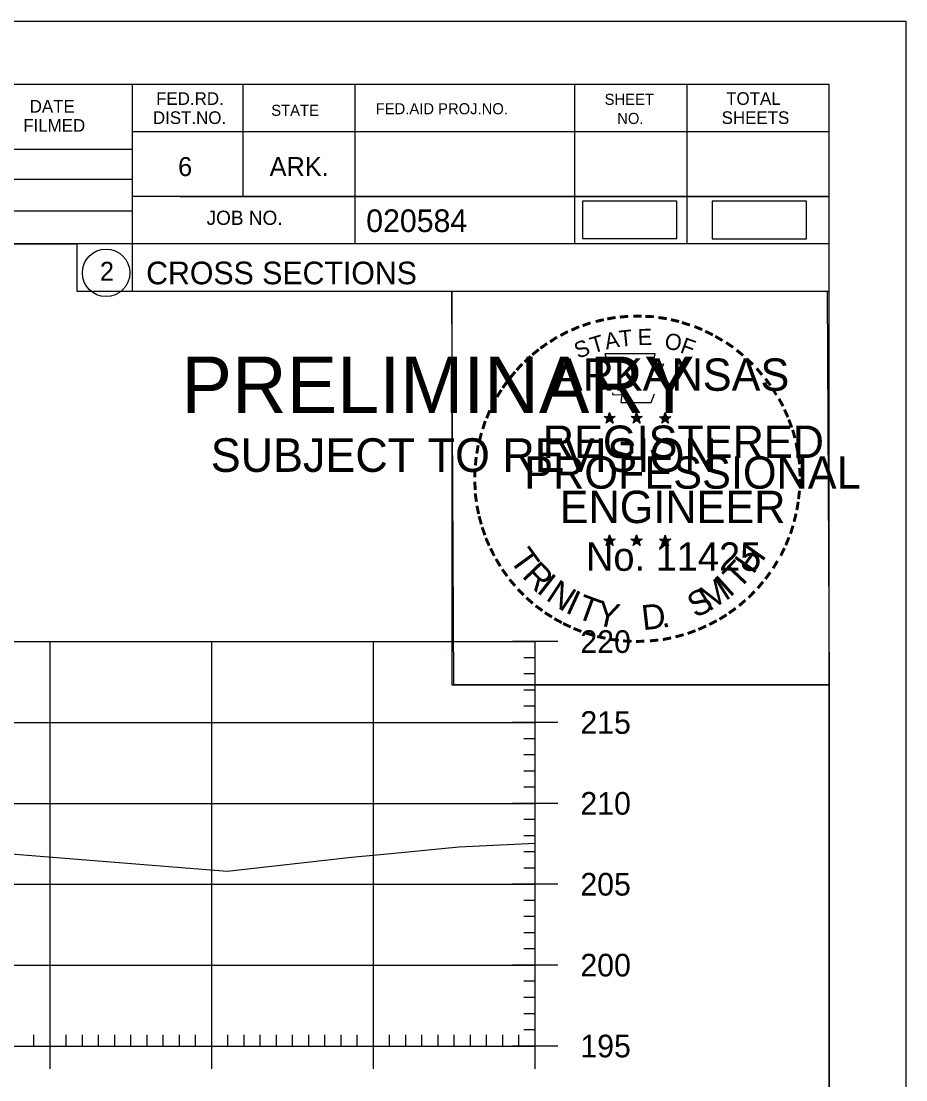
# Model space of a CAD drawing. Extents: x 1312042 to 1371461, y 379929 to 1834241.
# Drawn here: x 1371406.5 to 1371461.2, y 380076.8 to 380142.3 of the extents above; entities that cross this region are included whole.
import ezdxf

# ---------------------------------------------------------------- set-up
doc = ezdxf.new("R2010")
doc.units = 0
for name, color, linetype in [('Default', 7, 'Continuous'), ('R_Axis', 7, 'Continuous'), ('R_Axis Annot', 7, 'Continuous'), ('R_Border', 7, 'Continuous'), ('R_Border PE', 7, 'Continuous'), ('R_Border Prem', 7, 'Continuous'), ('R_Exist Surface', 7, 'Continuous'), ('R_Grid', 7, 'Continuous'), ('R_No Plot', 7, 'Continuous')]:
    doc.layers.add(name, color=color, linetype=linetype)

msp = doc.modelspace()

# ---------------------------------------------------------------- linework, layer by layer
at = {"layer": 'Default'}
for points in [[(1371441.216, 380128.825), (1371447.049, 380128.825), (1371447.049, 380131.136), (1371441.216, 380131.136)], [(1371449.239, 380128.818), (1371455.073, 380128.818), (1371455.073, 380131.128), (1371449.239, 380131.128)]]:
    msp.add_lwpolyline(points, close=True, dxfattribs=at)
at = {"layer": 'R_Axis'}
for p, q in [((1371439.677, 380103.909), (1371436.877, 380103.909)), ((1371438.277, 380078.909), (1371438.277, 380103.909)), ((1371438.277, 380102.909), (1371437.577, 380102.909)), ((1371438.277, 380101.909), (1371437.577, 380101.909)), ((1371438.277, 380100.909), (1371437.577, 380100.909)), ((1371438.277, 380099.909), (1371437.577, 380099.909)), ((1371439.677, 380098.909), (1371436.877, 380098.909)), ((1371438.277, 380097.909), (1371437.577, 380097.909)), ((1371438.277, 380096.909), (1371437.577, 380096.909)), ((1371438.277, 380095.909), (1371437.577, 380095.909)), ((1371438.277, 380094.909), (1371437.577, 380094.909)), ((1371439.677, 380093.909), (1371436.877, 380093.909)), ((1371438.277, 380092.909), (1371437.577, 380092.909)), ((1371438.277, 380091.909), (1371437.577, 380091.909)), ((1371438.277, 380090.909), (1371437.577, 380090.909)), ((1371438.277, 380089.909), (1371437.577, 380089.909)), ((1371439.677, 380088.909), (1371436.877, 380088.909)), ((1371438.277, 380087.909), (1371437.577, 380087.909)), ((1371438.277, 380086.909), (1371437.577, 380086.909)), ((1371438.277, 380085.909), (1371437.577, 380085.909)), ((1371438.277, 380084.909), (1371437.577, 380084.909)), ((1371439.677, 380083.909), (1371436.877, 380083.909)), ((1371438.277, 380082.909), (1371437.577, 380082.909)), ((1371438.277, 380081.909), (1371437.577, 380081.909)), ((1371438.277, 380080.909), (1371437.577, 380080.909)), ((1371408.277, 380077.509), (1371408.277, 380080.309)), ((1371418.277, 380077.509), (1371418.277, 380080.309)), ((1371428.277, 380077.509), (1371428.277, 380080.309)), ((1371438.277, 380079.909), (1371437.577, 380079.909)), ((1371438.277, 380077.509), (1371438.277, 380080.309)), ((1371407.277, 380078.909), (1371407.277, 380079.609)), ((1371409.277, 380078.909), (1371409.277, 380079.609)), ((1371410.277, 380078.909), (1371410.277, 380079.609)), ((1371411.277, 380078.909), (1371411.277, 380079.609)), ((1371412.277, 380078.909), (1371412.277, 380079.609)), ((1371413.277, 380078.909), (1371413.277, 380079.609)), ((1371414.277, 380078.909), (1371414.277, 380079.609)), ((1371415.277, 380078.909), (1371415.277, 380079.609)), ((1371416.277, 380078.909), (1371416.277, 380079.609)), ((1371417.277, 380078.909), (1371417.277, 380079.609)), ((1371419.277, 380078.909), (1371419.277, 380079.609)), ((1371420.277, 380078.909), (1371420.277, 380079.609)), ((1371421.277, 380078.909), (1371421.277, 380079.609)), ((1371422.277, 380078.909), (1371422.277, 380079.609)), ((1371423.277, 380078.909), (1371423.277, 380079.609)), ((1371424.277, 380078.909), (1371424.277, 380079.609)), ((1371425.277, 380078.909), (1371425.277, 380079.609)), ((1371426.277, 380078.909), (1371426.277, 380079.609)), ((1371427.277, 380078.909), (1371427.277, 380079.609)), ((1371429.277, 380078.909), (1371429.277, 380079.609)), ((1371430.277, 380078.909), (1371430.277, 380079.609)), ((1371431.277, 380078.909), (1371431.277, 380079.609)), ((1371432.277, 380078.909), (1371432.277, 380079.609)), ((1371433.277, 380078.909), (1371433.277, 380079.609)), ((1371434.277, 380078.909), (1371434.277, 380079.609)), ((1371435.277, 380078.909), (1371435.277, 380079.609)), ((1371436.277, 380078.909), (1371436.277, 380079.609)), ((1371437.277, 380078.909), (1371437.277, 380079.609)), ((1371158.277, 380078.909), (1371438.277, 380078.909)), ((1371439.677, 380078.909), (1371436.877, 380078.909))]:
    msp.add_line(p, q, dxfattribs=at)
at = {"layer": 'R_Border'}
for p, q in [((1371140.277, 380138.369), (1371456.457, 380138.369)), ((1371413.357, 380138.369), (1371413.357, 380125.569)), ((1371420.197, 380138.369), (1371420.197, 380131.429)), ((1371427.137, 380138.369), (1371427.137, 380128.489)), ((1371440.717, 380138.369), (1371440.717, 380128.489)), ((1371447.657, 380138.369), (1371447.657, 380128.489)), ((1371456.457, 379932.909), (1371456.457, 380138.369)), ((1371456.457, 380135.429), (1371413.357, 380135.429)), ((1371456.457, 380135.449), (1371456.457, 380135.449)), ((1371374.197, 380134.349), (1371413.357, 380134.349)), ((1371374.197, 380132.489), (1371413.357, 380132.489)), ((1371456.457, 380131.429), (1371413.357, 380131.429)), ((1371416.317, 380131.429), (1371456.457, 380131.429)), ((1371374.197, 380130.549), (1371413.357, 380130.549)), ((1371456.457, 380128.489), (1371374.197, 380128.489)), ((1371413.357, 380125.569), (1371456.457, 380125.569))]:
    msp.add_line(p, q, dxfattribs=at)
msp.add_circle((1371411.743, 380126.705), 1.467, dxfattribs=at)
at = {"layer": 'R_Border PE'}
for p, q in [((1371442.541, 380117.824), (1371442.89, 380117.713)), ((1371442.541, 380117.824), (1371442.794, 380117.779)), ((1371442.541, 380117.824), (1371442.778, 380117.702)), ((1371442.89, 380118.078), (1371442.849, 380117.826)), ((1371442.89, 380117.713), (1371442.89, 380118.078)), ((1371442.89, 380118.078), (1371442.939, 380117.828)), ((1371443.237, 380117.824), (1371442.89, 380117.713)), ((1371443.237, 380117.824), (1371442.951, 380117.775)), ((1371443.237, 380117.824), (1371443.033, 380117.722)), ((1371444.211, 380117.824), (1371444.56, 380117.713)), ((1371444.211, 380117.824), (1371444.464, 380117.779)), ((1371444.211, 380117.824), (1371444.448, 380117.702)), ((1371444.56, 380118.078), (1371444.519, 380117.826)), ((1371444.56, 380117.713), (1371444.56, 380118.078)), ((1371444.56, 380118.078), (1371444.609, 380117.828)), ((1371444.907, 380117.824), (1371444.56, 380117.713)), ((1371444.907, 380117.824), (1371444.621, 380117.775)), ((1371444.907, 380117.824), (1371444.703, 380117.722)), ((1371445.975, 380117.812), (1371446.324, 380117.701)), ((1371445.975, 380117.812), (1371446.228, 380117.767)), ((1371445.975, 380117.812), (1371446.212, 380117.69)), ((1371446.324, 380118.066), (1371446.283, 380117.814)), ((1371446.324, 380117.701), (1371446.324, 380118.066)), ((1371446.324, 380118.066), (1371446.373, 380117.816)), ((1371446.671, 380117.812), (1371446.324, 380117.701)), ((1371446.671, 380117.812), (1371446.385, 380117.763)), ((1371446.671, 380117.812), (1371446.467, 380117.71)), ((1371442.674, 380117.416), (1371442.89, 380117.713)), ((1371442.674, 380117.416), (1371442.8, 380117.66)), ((1371442.674, 380117.416), (1371442.888, 380117.633)), ((1371443.103, 380117.416), (1371442.888, 380117.63)), ((1371443.103, 380117.416), (1371442.89, 380117.713)), ((1371443.103, 380117.416), (1371442.966, 380117.707)), ((1371444.344, 380117.416), (1371444.56, 380117.713)), ((1371444.344, 380117.416), (1371444.47, 380117.66)), ((1371444.344, 380117.416), (1371444.558, 380117.633)), ((1371444.773, 380117.416), (1371444.558, 380117.63)), ((1371444.773, 380117.416), (1371444.56, 380117.713)), ((1371444.773, 380117.416), (1371444.636, 380117.707)), ((1371446.108, 380117.404), (1371446.324, 380117.701)), ((1371446.108, 380117.404), (1371446.234, 380117.648)), ((1371446.108, 380117.404), (1371446.322, 380117.621)), ((1371446.537, 380117.404), (1371446.322, 380117.618)), ((1371446.537, 380117.404), (1371446.324, 380117.701)), ((1371446.537, 380117.404), (1371446.4, 380117.695)), ((1371442.537, 380110.251), (1371442.886, 380110.14)), ((1371442.537, 380110.251), (1371442.79, 380110.206)), ((1371442.537, 380110.251), (1371442.774, 380110.129)), ((1371442.67, 380109.843), (1371442.886, 380110.14)), ((1371442.67, 380109.843), (1371442.796, 380110.087)), ((1371442.67, 380109.843), (1371442.884, 380110.06)), ((1371442.886, 380110.505), (1371442.845, 380110.253)), ((1371443.099, 380109.843), (1371442.884, 380110.057)), ((1371442.886, 380110.14), (1371442.886, 380110.505)), ((1371442.886, 380110.505), (1371442.935, 380110.255)), ((1371443.233, 380110.251), (1371442.886, 380110.14)), ((1371443.099, 380109.843), (1371442.886, 380110.14)), ((1371443.233, 380110.251), (1371442.947, 380110.202)), ((1371443.099, 380109.843), (1371442.962, 380110.134)), ((1371443.233, 380110.251), (1371443.029, 380110.149)), ((1371444.206, 380110.251), (1371444.555, 380110.14)), ((1371444.206, 380110.251), (1371444.459, 380110.206)), ((1371444.206, 380110.251), (1371444.443, 380110.129)), ((1371444.339, 380109.843), (1371444.555, 380110.14)), ((1371444.339, 380109.843), (1371444.465, 380110.087)), ((1371444.339, 380109.843), (1371444.553, 380110.06)), ((1371444.555, 380110.505), (1371444.514, 380110.253)), ((1371444.768, 380109.843), (1371444.553, 380110.057)), ((1371444.555, 380110.14), (1371444.555, 380110.505)), ((1371444.555, 380110.505), (1371444.604, 380110.255)), ((1371444.902, 380110.251), (1371444.555, 380110.14)), ((1371444.768, 380109.843), (1371444.555, 380110.14)), ((1371444.902, 380110.251), (1371444.616, 380110.202)), ((1371444.768, 380109.843), (1371444.631, 380110.134)), ((1371444.902, 380110.251), (1371444.698, 380110.149)), ((1371445.973, 380110.241), (1371446.322, 380110.13)), ((1371445.973, 380110.241), (1371446.226, 380110.196)), ((1371445.973, 380110.241), (1371446.21, 380110.119)), ((1371446.106, 380109.833), (1371446.322, 380110.13)), ((1371446.106, 380109.833), (1371446.232, 380110.077)), ((1371446.106, 380109.833), (1371446.32, 380110.05)), ((1371446.322, 380110.495), (1371446.281, 380110.243)), ((1371446.535, 380109.833), (1371446.32, 380110.047)), ((1371446.322, 380110.13), (1371446.322, 380110.495)), ((1371446.322, 380110.495), (1371446.371, 380110.245)), ((1371446.669, 380110.241), (1371446.322, 380110.13)), ((1371446.535, 380109.833), (1371446.322, 380110.13)), ((1371446.669, 380110.241), (1371446.383, 380110.192)), ((1371446.535, 380109.833), (1371446.398, 380110.124)), ((1371446.669, 380110.241), (1371446.465, 380110.139))]:
    msp.add_line(p, q, dxfattribs=at)
for points in [[(1371442.582, 380121.702), (1371442.851, 380120.875)], [(1371446.093, 380120.78), (1371446.235, 380121.064), (1371445.55, 380121.04), (1371445.698, 380121.702), (1371442.582, 380121.702)], [(1371443.074, 380119.279), (1371443.074, 380119.192), (1371443.637, 380119.173), (1371443.583, 380118.7), (1371445.453, 380118.7), (1371445.654, 380119.236)], [(1371442.89, 380118.078), (1371443.103, 380117.416), (1371442.541, 380117.824), (1371443.237, 380117.824), (1371442.674, 380117.416), (1371442.89, 380118.078)], [(1371444.56, 380118.078), (1371444.773, 380117.416), (1371444.211, 380117.824), (1371444.907, 380117.824), (1371444.344, 380117.416), (1371444.56, 380118.078)], [(1371446.324, 380118.066), (1371446.537, 380117.404), (1371445.975, 380117.812), (1371446.671, 380117.812), (1371446.108, 380117.404), (1371446.324, 380118.066)], [(1371442.886, 380110.505), (1371443.099, 380109.843), (1371442.537, 380110.251), (1371443.233, 380110.251), (1371442.67, 380109.843), (1371442.886, 380110.505)], [(1371444.555, 380110.505), (1371444.768, 380109.843), (1371444.206, 380110.251), (1371444.902, 380110.251), (1371444.339, 380109.843), (1371444.555, 380110.505)], [(1371446.322, 380110.495), (1371446.535, 380109.833), (1371445.973, 380110.241), (1371446.669, 380110.241), (1371446.106, 380109.833), (1371446.322, 380110.495)]]:
    msp.add_lwpolyline(points, dxfattribs=at)
for centre, radius in [((1371442.889, 380117.712), 0.172), ((1371442.889, 380117.712), 0.145), ((1371442.889, 380117.712), 0.116), ((1371442.889, 380117.712), 0.0991), ((1371442.889, 380117.712), 0.0747), ((1371442.889, 380117.712), 0.0495), ((1371442.889, 380117.712), 0.0296), ((1371444.559, 380117.712), 0.172), ((1371444.559, 380117.712), 0.145), ((1371444.559, 380117.712), 0.116), ((1371444.559, 380117.712), 0.0991), ((1371444.559, 380117.712), 0.0747), ((1371444.559, 380117.712), 0.0495), ((1371444.559, 380117.712), 0.0296), ((1371446.323, 380117.7), 0.172), ((1371446.323, 380117.7), 0.145), ((1371446.323, 380117.7), 0.116), ((1371446.323, 380117.7), 0.0991), ((1371446.323, 380117.7), 0.0747), ((1371446.323, 380117.7), 0.0495), ((1371446.323, 380117.7), 0.0296), ((1371442.885, 380110.139), 0.172), ((1371442.885, 380110.139), 0.145), ((1371442.885, 380110.139), 0.116), ((1371442.885, 380110.139), 0.0991), ((1371442.885, 380110.139), 0.0747), ((1371442.885, 380110.139), 0.0495), ((1371442.885, 380110.139), 0.0296), ((1371444.554, 380110.139), 0.172), ((1371444.554, 380110.139), 0.145), ((1371444.554, 380110.139), 0.116), ((1371444.554, 380110.139), 0.0991), ((1371444.554, 380110.139), 0.0747), ((1371444.554, 380110.139), 0.0495), ((1371444.554, 380110.139), 0.0296), ((1371446.321, 380110.129), 0.172), ((1371446.321, 380110.129), 0.145), ((1371446.321, 380110.129), 0.116), ((1371446.321, 380110.129), 0.0991), ((1371446.321, 380110.129), 0.0747), ((1371446.321, 380110.129), 0.0495), ((1371446.321, 380110.129), 0.0296)]:
    msp.add_circle(centre, radius, dxfattribs=at)
at = {"layer": 'R_Exist Surface'}
msp.add_lwpolyline([(1371352.617, 380089.688), (1371369.575, 380089.81), (1371379.307, 380089.668), (1371394.991, 380090.832), (1371396.306, 380090.839), (1371403.519, 380090.982), (1371419.223, 380089.723), (1371426.924, 380090.582), (1371429.352, 380090.807), (1371433.568, 380091.216), (1371438.277, 380091.459)], dxfattribs=at)
at = {"layer": 'R_Grid'}
for p, q in [((1371158.277, 380103.909), (1371438.277, 380103.909)), ((1371408.277, 380078.909), (1371408.277, 380103.909)), ((1371418.277, 380078.909), (1371418.277, 380103.909)), ((1371428.277, 380078.909), (1371428.277, 380103.909)), ((1371438.277, 380078.909), (1371438.277, 380103.909)), ((1371158.277, 380098.909), (1371438.277, 380098.909)), ((1371158.277, 380093.909), (1371438.277, 380093.909)), ((1371158.277, 380088.909), (1371438.277, 380088.909)), ((1371158.277, 380083.909), (1371438.277, 380083.909)), ((1371158.277, 380078.909), (1371438.277, 380078.909))]:
    msp.add_line(p, q, dxfattribs=at)
at = {"layer": 'R_No Plot'}
for p, q in [((1371127.876, 380142.263), (1371461.209, 380142.263)), ((1371432.491, 380103.113), (1371432.491, 380103.113))]:
    msp.add_line(p, q, dxfattribs=at)
for points in [[(1371127.869, 380142.263), (1371461.209, 380142.263), (1371461.209, 379928.926), (1371127.869, 379928.926)], [(1371374.197, 380138.369), (1371374.197, 380128.489), (1371409.929, 380128.489), (1371409.929, 380125.569), (1371433.128, 380125.569), (1371433.128, 380101.236), (1371456.457, 380101.236), (1371456.457, 379932.909), (1371140.277, 379932.909), (1371140.277, 380138.369)], [(1371433.128, 380125.569), (1371456.336, 380125.569), (1371456.457, 380101.236), (1371433.249, 380101.236)]]:
    msp.add_lwpolyline(points, close=True, dxfattribs=at)

# ---------------------------------------------------------------- texts
at = {"layer": 'R_Axis Annot'}
for s, p in [('220', (1371441.077, 380103.209)), ('215', (1371441.077, 380098.209)), ('210', (1371441.077, 380093.209)), ('205', (1371441.077, 380088.209)), ('200', (1371441.077, 380083.209)), ('195', (1371441.077, 380078.209))]:
    msp.add_text(s, height=1.4, dxfattribs=at).set_placement(p)
at = {"layer": 'R_Border'}
for s, height, p in [('DATE', 0.7819, (1371407.017, 380136.609)), ('FED.RD.', 0.7819, (1371414.837, 380137.089)), ('SHEET', 0.684, (1371442.577, 380137.089)), ('TOTAL', 0.7819, (1371450.097, 380137.089)), ('STATE', 0.684, (1371421.957, 380136.409)), ('FED.AID PROJ.NO.', 0.684, (1371428.417, 380136.509)), ('FILMED', 0.7819, (1371406.617, 380135.429)), ('DIST.NO.', 0.7819, (1371414.637, 380135.909)), ('NO.', 0.684, (1371443.357, 380135.909)), ('SHEETS', 0.7819, (1371449.817, 380135.909)), ('6', 1.172, (1371416.197, 380132.689)), ('ARK.', 1.1723, (1371421.857, 380132.689)), ('JOB NO.', 0.8792, (1371417.957, 380129.669)), ('020584', 1.4, (1371427.833, 380129.228)), ('2', 1.172, (1371411.361, 380126.218)), ('CROSS SECTIONS', 1.4, (1371414.22, 380125.999))]:
    msp.add_text(s, height=height, rotation=360, dxfattribs=at).set_placement(p)
at = {"layer": 'R_Border PE'}
for s, height, rotation, p in [('-', 1.6, 19.17608, (1371441.33, 380122.829)), ('-', 1.6, 13.63015, (1371442.08, 380123.07)), ('-', 1.6, 10.21935, (1371442.758, 380123.232)), ('-', 1.6, 5.89682, (1371443.487, 380123.342)), ('-', 1.6, 0.18623, (1371444.259, 380123.414)), ('-', 1.6, 357.74304, (1371444.982, 380123.401)), ('-', 1.6, 352.16172, (1371445.726, 380123.345)), ('-', 1.6, 347.20489, (1371446.445, 380123.231)), ('-', 1.6, 342.3362, (1371447.08, 380123.076)), ('-', 1.6, 28.79182, (1371440.063, 380122.243)), ('-', 1.6, 24.30721, (1371440.696, 380122.56)), ('A', 1, 11.21318, (1371442.677, 380121.962)), ('T', 1, 6.02276, (1371443.526, 380122.128)), ('E', 1, 0.83234, (1371444.631, 380122.238)), ('O', 1, 350.4515, (1371446.235, 380122.028)), ('-', 1.6, 337.85509, (1371447.815, 380122.853)), ('-', 1.6, 334.12109, (1371448.446, 380122.582)), ('-', 1.6, 36.23174, (1371438.888, 380121.478)), ('-', 1.6, 34.06357, (1371439.466, 380121.873)), ('S', 1, 21.59401, (1371440.937, 380121.38)), ('T', 1, 16.4036, (1371441.851, 380121.711)), ('F', 1, 340.07066, (1371447.189, 380121.8)), ('-', 1.6, 329.64089, (1371449.025, 380122.299)), ('-', 1.6, 325.86266, (1371449.668, 380121.938)), ('-', 1.6, 38.95066, (1371438.412, 380121.1)), ('-', 1.6, 320.52971, (1371450.278, 380121.512)), ('-', 1.6, 48.42305, (1371437.531, 380120.205)), ('-', 1.6, 42.96224, (1371437.979, 380120.683)), ('ARKANSAS', 2, 360, (1371439.435, 380119.414)), ('-', 1.6, 315.57859, (1371450.877, 380121.024)), ('-', 1.6, 50.61417, (1371437.128, 380119.719)), ('-', 1.6, 309.87973, (1371451.446, 380120.474)), ('-', 1.6, 54.23247, (1371436.715, 380119.152)), ('-', 1.6, 306.65218, (1371451.971, 380119.872)), ('-', 1.6, 58.07063, (1371436.39, 380118.625)), ('-', 1.4, 303.67529, (1371452.457, 380119.304)), ('-', 1.6, 62.87135, (1371436.077, 380118.011)), ('-', 1.6, 299.66835, (1371452.776, 380118.697)), ('-', 1.6, 67.77427, (1371435.818, 380117.4)), ('-', 1.6, 294.66279, (1371453.1, 380118.085)), ('-', 1.6, 72.39447, (1371435.599, 380116.77)), ('REGISTERED', 2, 360, (1371438.757, 380115.265)), ('DWB', 0.01, 360, (1371442.878, 380117.708)), ('DWB', 0.01, 360, (1371444.547, 380117.708)), ('DWB', 0.01, 360, (1371446.312, 380117.697)), ('-', 1.6, 290.57283, (1371453.357, 380117.508)), ('-', 1.6, 75.46096, (1371435.402, 380116.056)), ('-', 1.6, 285.12326, (1371453.591, 380116.928)), ('-', 1.6, 81.20126, (1371435.27, 380115.343)), ('-', 1.6, 280.54934, (1371453.791, 380116.186)), ('-', 1.6, 85.18634, (1371435.194, 380114.652)), ('PROFESSIONAL', 2, 360, (1371437.609, 380113.361)), ('-', 1.6, 276.59616, (1371453.953, 380115.418)), ('-', 1.6, 89.06224, (1371435.169, 380113.951)), ('-', 1.6, 274.33011, (1371454.013, 380114.696)), ('-', 1.6, 269.94067, (1371454.047, 380114.064)), ('-', 1.6, 94.19588, (1371435.204, 380113.226)), ('ENGINEER', 2, 360, (1371439.796, 380111.236)), ('-', 1.6, 263.5172, (1371454.028, 380113.398)), ('-', 1.6, 98.94793, (1371435.276, 380112.559)), ('-', 1.6, 260.99529, (1371453.957, 380112.744)), ('-', 1.6, 101.71495, (1371435.411, 380111.826)), ('-', 1.6, 105.45785, (1371435.573, 380111.231)), ('-', 1.6, 255.7626, (1371453.847, 380112.066)), ('-', 1.6, 109.08742, (1371435.788, 380110.6)), ('-', 1.6, 252.86809, (1371453.666, 380111.346)), ('-', 1.6, 114.06432, (1371436.042, 380110.004)), ('No. 11425', 1.757, 360, (1371441.424, 380108.285)), ('DWB', 0.01, 360, (1371442.874, 380110.135)), ('DWB', 0.01, 360, (1371444.543, 380110.135)), ('DWB', 0.01, 360, (1371446.31, 380110.125)), ('H', 1.54, 54.60883, (1371451.766, 380108.013)), ('-', 1.6, 247.88866, (1371453.443, 380110.673)), ('-', 1.6, 115.72885, (1371436.347, 380109.386)), ('T', 1.54, 306.04056, (1371436.646, 380108.978)), ('-', 1.6, 244.61971, (1371453.181, 380110.044)), ('-', 1.6, 120.44712, (1371436.704, 380108.8)), ('R', 1.54, 314.00497, (1371437.409, 380107.93)), ('T', 1.54, 46.64442, (1371450.877, 380107.071)), ('-', 1.6, 239.07125, (1371452.787, 380109.292)), ('-', 1.6, 125.89344, (1371437.107, 380108.239)), ('I', 1.54, 321.96938, (1371438.309, 380106.998)), ('I', 1.54, 42.11359, (1371450.315, 380106.593)), ('-', 1.6, 233.84524, (1371452.385, 380108.639)), ('-', 1.6, 130.71812, (1371437.569, 380107.687)), ('N', 1.54, 326.50021, (1371438.876, 380106.527)), ('M', 1.54, 32.65632, (1371449.031, 380105.746)), ('-', 1.6, 231.25377, (1371451.955, 380108.073)), ('-', 1.6, 134.22381, (1371438.086, 380107.142)), ('-', 1.6, 138.93382, (1371438.611, 380106.678)), ('I', 1.54, 335.36034, (1371440.084, 380105.741)), ('T', 1.54, 339.89117, (1371440.745, 380105.413)), ('S', 1.54, 26.9312, (1371448.192, 380105.34)), ('-', 1.6, 225.76533, (1371451.476, 380107.509)), ('-', 1.6, 144.64634, (1371439.167, 380106.272)), ('Y', 1.54, 347.85558, (1371441.962, 380104.968)), ('D', 1.54, 6.39691, (1371444.947, 380104.609)), ('-', 1.6, 215.73633, (1371450.405, 380106.528)), ('-', 1.6, 221.08509, (1371450.954, 380107)), ('-', 1.6, 148.08978, (1371439.728, 380105.901)), ('-', 1.6, 151.57039, (1371440.307, 380105.576)), ('-', 1.6, 212.24909, (1371449.871, 380106.141)), ('-', 1.6, 154.60019, (1371440.829, 380105.329)), ('-', 1.6, 158.56121, (1371441.453, 380105.075)), ('.', 1.54, 13.76417, (1371446.139, 380104.737)), ('-', 1.6, 200.71842, (1371448.07, 380105.203)), ('-', 1.6, 204.25161, (1371448.689, 380105.476)), ('-', 1.6, 207.35684, (1371449.313, 380105.795)), ('-', 1.6, 162.79826, (1371442.14, 380104.862)), ('-', 1.6, 167.55551, (1371442.855, 380104.698)), ('-', 1.6, 173.11546, (1371443.627, 380104.588)), ('-', 1.6, 176.51827, (1371444.375, 380104.535)), ('-', 1.6, 181.59176, (1371445.119, 380104.554)), ('-', 1.6, 185.81666, (1371445.928, 380104.63)), ('-', 1.6, 191.28576, (1371446.664, 380104.762)), ('-', 1.6, 195.47429, (1371447.393, 380104.961))]:
    msp.add_text(s, height=height, rotation=rotation, dxfattribs=at).set_placement(p)
at = {"layer": 'R_Border Prem'}
for s, height, p in [('PRELIMINARY', 3.5, (1371416.408, 380118.032)), ('DWB', 0.01, (1371417.154, 380119.881)), ('SUBJECT TO REVISION', 2.07511, (1371418.217, 380114.403))]:
    msp.add_text(s, height=height, rotation=360, dxfattribs=at).set_placement(p)

doc.saveas('drawing.dxf')
